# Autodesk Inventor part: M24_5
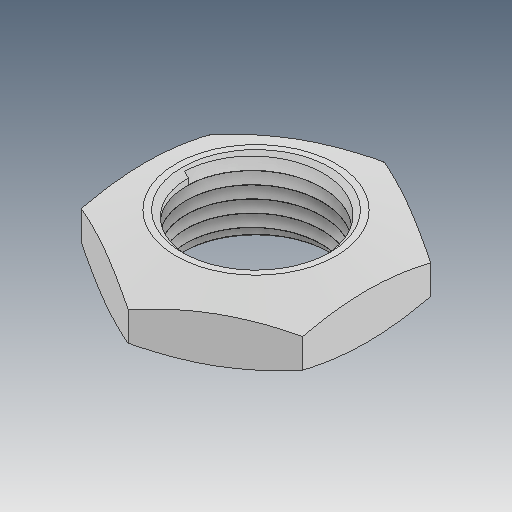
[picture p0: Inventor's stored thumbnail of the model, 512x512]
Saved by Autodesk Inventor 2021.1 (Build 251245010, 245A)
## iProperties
Created: 2019-05
Part Number: M24_5
Material: Ogólny
Document SubType Name: Modeling
Designer: user
Density: 1 g/cm^3
Appearance: Domyślna
Author: user
Revision Number: ÈÎºÎ
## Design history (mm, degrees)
feature "ÊäÈë1"
node "Bryła1"
